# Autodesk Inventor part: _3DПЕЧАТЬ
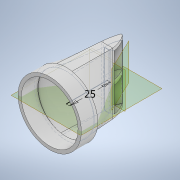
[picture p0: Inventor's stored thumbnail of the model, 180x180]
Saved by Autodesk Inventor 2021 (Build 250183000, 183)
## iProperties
Created: 2022-02
Part Number: _3DПЕЧАТЬ
Material: Типовые
Document SubType Name: Modeling
Designer: Evgeniy
Density: 1 g/cm^3
Appearance: По умолчанию
Author: Evgeniy
Part Number: pilisos
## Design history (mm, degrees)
sketch "Эскиз1"
  geometry: C1 r 19.3 at (0, 0); 1 further point
  constraints: 1 centre point, 1 coincident
  dimensions: "d0" = 38.6 diameter of C1
sketch "Эскиз2"
  geometry: L1 (0, 0)-(0, -25)
  constraints: 2 end point, 1 vertical
  dimensions: "d1" = 25 distance of L1.start L1.end
node "РабПлоскость1"
sketch "Эскиз3"
  geometry: L1 (3.5, -18.801)-(-3.5, -18.801); L2 (-3.5, -18.801)-(-3.5, 18.699); L3 (-3.5, 18.699)-(3.5, 18.699); L4 (3.5, 18.699)-(3.5, -18.801); 1 further point
  constraints: 8 end point, 2 parallel, 1 horizontal, 1 perpendicular
  dimensions: "d2" = 7 distance of L2.end L3.end; "d3" = 37.5 distance between parallel lines of L1 L3; "d4" = 3.5 distance from line of L4 point (0, 0)
feature "Лофт1" sketch "Эскиз3" dims "d5" = 0, "d6" = 90 deg, "d7" = 0, "d8" = 90 deg
feature "Оболочка1" dims "d9" = 2
sketch "Эскиз4"
  geometry: C1 r 17.3 at (0, 0); C2 r 19.3 at (0, 0); A1 r 19.3 centre (0, 0) between (-4.72, 18.714) and (-4.72, -18.714) reference; 3 further points
  constraints: 2 centre point, 2 coincident
  dimensions: "d10" = 34.6 diameter of C1
extrude "Выдавливание1" join sketch "Эскиз4" distance "d11" = 10; taper "d12" = 0 deg
sketch "Эскиз5"
  geometry: 1 further point
sketch "Эскиз6"
  geometry: L1 (5.024, 2.04)-(1.911, 2.04); L2 (1.911, 2.04)-(1.911, 35.453); L3 (1.911, 35.453)-(5.024, 35.453); L4 (5.024, 35.453)-(5.024, 2.04); 1 further point
  constraints: 8 end point, 2 parallel, 1 horizontal, 1 perpendicular
extrude "Выдавливание2" cut sketch "Эскиз6" distance "d13" = 10; taper "d14" = 0 deg
sketch "Эскиз7"
  geometry: L1 (4.962, 35.453)-(5.024, 35.453) reference; L2 (1.911, 2.04)-(1.911, 35.453) reference; L3 (5.024, 35.453)-(1.911, 35.453); L4 (1.911, 35.453)-(1.911, 2.04); L5 (1.911, 2.04)-(5.024, 2.04); L6 (5.024, 2.04)-(5.024, 35.453); L7 (7, 0)-(7, 37.5) reference; L8 (0, 37.5)-(0, 0) reference; L9 (7, 37.5)-(0, 37.5); L10 (0, 37.5)-(0, 0); L11 (0, 0)-(7, 0); L12 (7, 0)-(7, 37.5); 3 further points
  constraints: 16 end point, 4 parallel, 2 horizontal, 2 perpendicular
extrude "Выдавливание3" join sketch "Эскиз7" distance "d15" = 10; taper "d16" = 0 deg
sketch "Эскиз8"
  geometry: L1 (-0.116, 35)-(0, 10) reference; L2 (0, 10)-(0, 0) reference; L3 (0, 10)-(0, 0); L4 (0, 0)-(1.008, 0); L5 (0, 0)-(7, 0) reference; L6 (0, 10)-(0, 0); L7 (1.008, 0)-(0, 10); L8 (7, 0)-(0, 0) reference; L9 (7, 10)-(7, 0) reference; L10 (3.001, 0)-(7, 0); L11 (9.308, 35)-(7, 10) reference; L12 (7, 0)-(7, 10); A1 r 20.942 centre (-13.79, 12.514) between (3.001, 0) and (7, 10); 2 further points
  constraints: 12 end point, 2 point on circle, 2 point on line, 1 centre point, 1 collinear, 1 perpendicular, 1 vertical
extrude "Выдавливание4" cut sketch "Эскиз8" distance "d17" = 50; taper "d18" = 0 deg
sketch "Эскиз9"
  geometry: L1 (2.715, -25)-(-3.5, -25) reference; A1 r 20.942 centre (17.29, -22.486) between (-3.5, -25) and (0.499, -35) reference; A2 r 11.979 centre (-11.97, -25.472) between (-1.615, -31.495) and (0, -25); 1 further point
  constraints: 3 point on circle, 1 centre point, 1 point on line
node "РабПлоскость2"
sketch "Эскиз10"
  geometry: L1 (16.762, 5.852)-(-16.652, 5.852) reference; L2 (16.762, 5.852)-(-16.68, 5.852); L3 (-16.68, 5.852)-(-16.68, -3.202); L4 (-16.68, -3.202)-(16.762, -3.202); L5 (16.762, -3.202)-(16.762, 5.852); 1 further point
  constraints: 8 end point, 2 parallel, 1 horizontal, 1 perpendicular
sketch "Эскиз11"
  geometry: L1 (-5.024, 35.453)-(-5.024, 2.04) reference; L2 (-1.911, 2.04)-(-5.024, 2.04); L3 (-5.024, 2.04)-(-5.024, 35.453); L4 (-5.024, 35.453)-(-1.911, 35.453); L5 (-1.911, 35.453)-(-1.911, 2.04); 1 further point
  constraints: 8 end point, 2 parallel, 1 horizontal, 1 perpendicular
feature "Лофт2" dims "d19" = 0, "d20" = 90 deg, "d21" = 0, "d22" = 90 deg, "d23" = 0, "d24" = 90 deg
  node "Ребра1"
sketch "Эскиз12"
  geometry: L1 (1.008, -10)-(0, 0) reference; L2 (3.001, -10)-(1.008, -10) reference; L3 (2.005, -10)-(1.008, -10); A1 r 45.071 centre (44.91, 3.803) between (0, 0) and (2.005, -10); 2 further points
  constraints: 2 end point, 2 point on circle, 1 centre point, 1 collinear, 1 midpoint
extrude "Выдавливание5" cut sketch "Эскиз12" distance "d25" = 50; taper "d26" = 0 deg
node "РабПлоскость3"
sketch "Эскиз13"
  geometry: L1 (2.397, -25)-(-3.5, -25) reference; L2 (2.15, -25)-(-2.289, -25); A1 r 20.942 centre (-17.29, -22.486) between (-0.499, -35) and (3.5, -25) reference; A2 r 16.48 centre (14.143, -26.264) between (-2.289, -25) and (-0.134, -34.495); A3 r 3.435 centre (4.755, -22.76) between (2.15, -25) and (3.385, -25.91); A4 r 21.234 centre (-17.547, -22.344) between (-0.134, -34.495) and (3.385, -25.91); 2 further points
  constraints: 7 point on circle, 3 centre point, 2 end point, 1 horizontal, 1 point on line
extrude "Выдавливание6" join sketch "Эскиз13" stored distance "d27" = 3; taper "d28" = 0 deg
node "Твердое тело1"
